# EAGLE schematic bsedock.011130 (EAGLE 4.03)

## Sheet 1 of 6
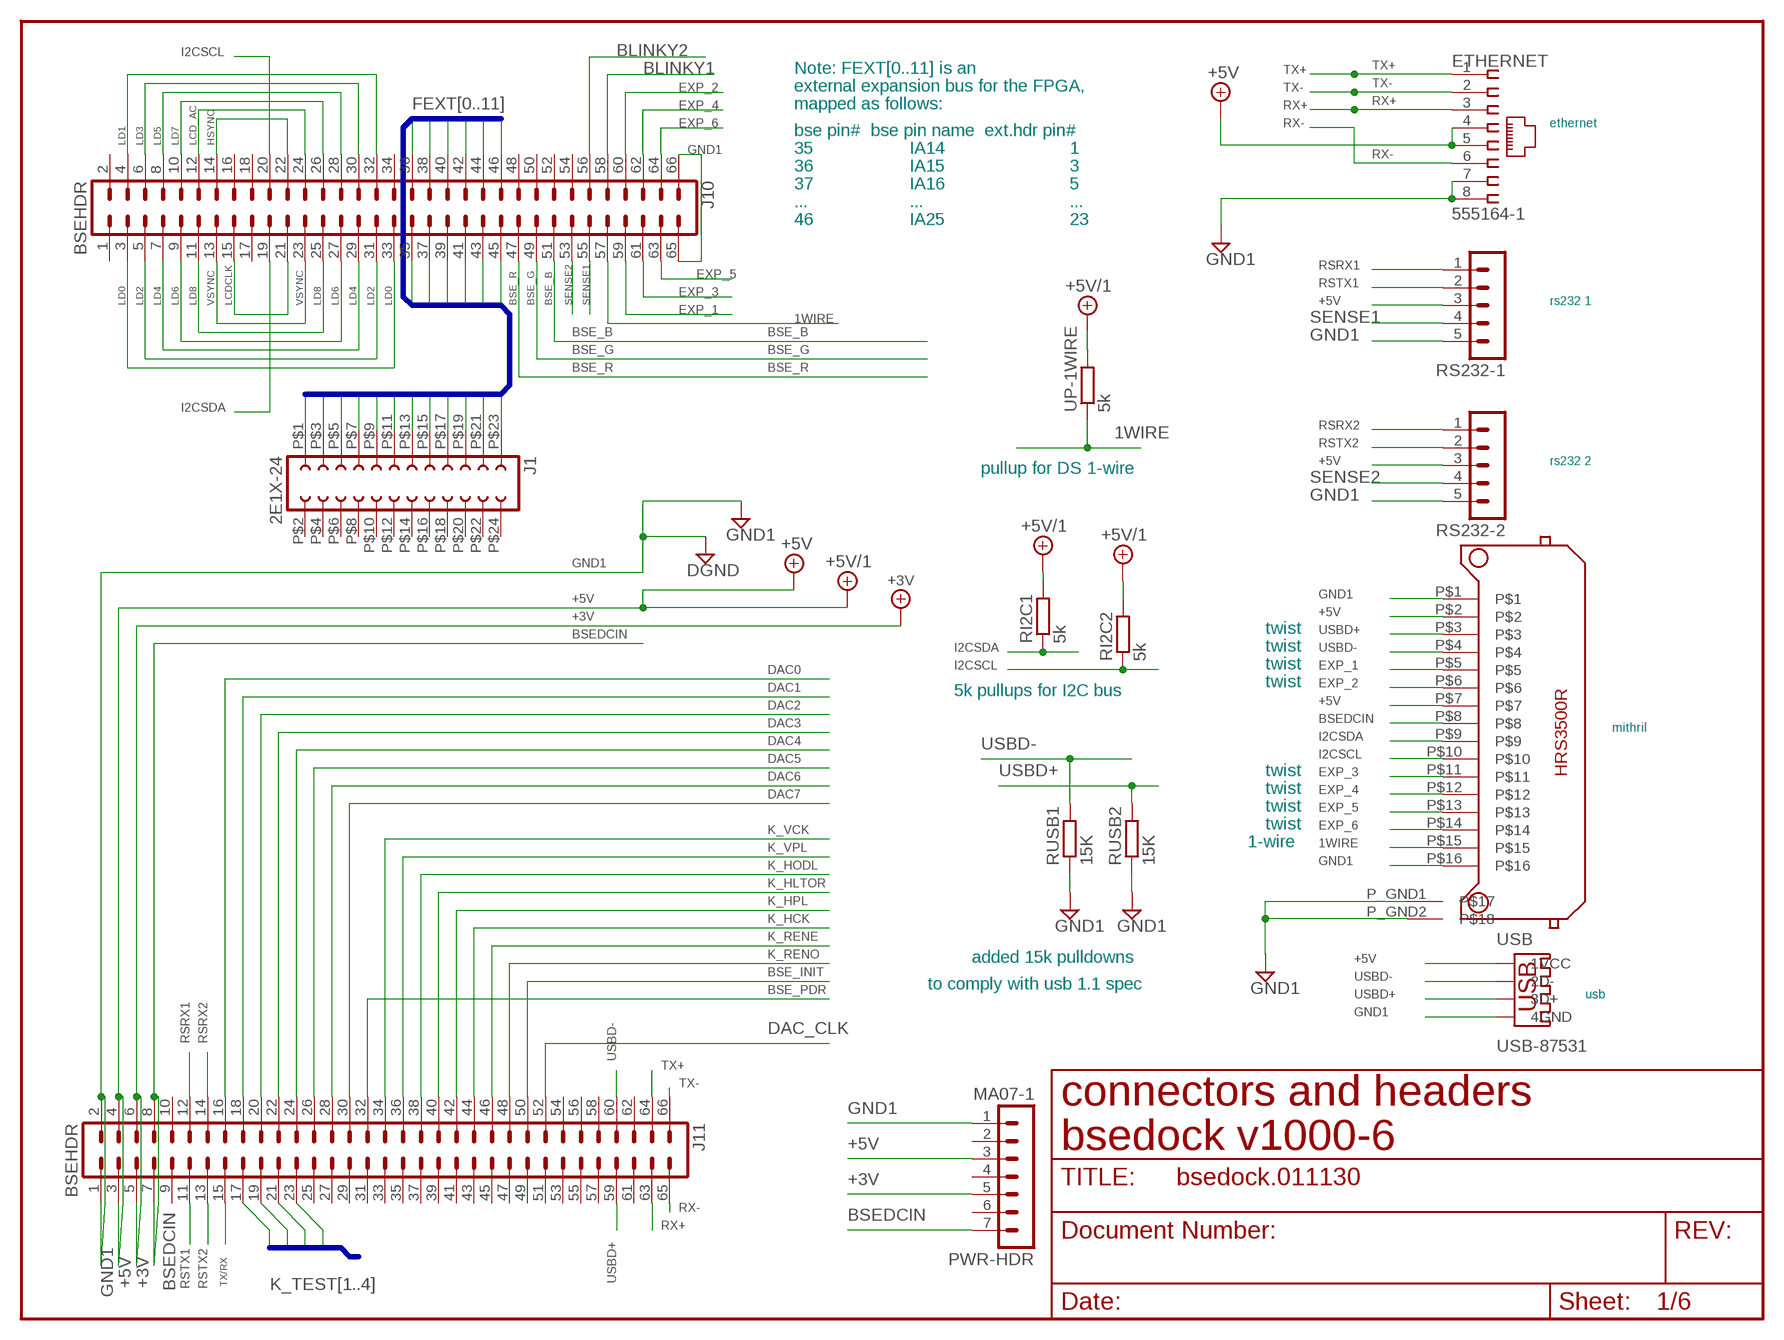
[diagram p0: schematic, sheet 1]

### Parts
BODY-BUS  HRS3500R  [HRS3500]
ETHERNET  555164-1  [555164-1]
J1  2E1X-24  [2E1X-24]
J10  BSEHDR  [BSEHDR]
J11  BSEHDR  [BSEHDR]
PWR-HDR  MA07-1  [MA07-1]
RI2C1  5k  R1206  [R1206]
RI2C2  5k  R1206  [R1206]
RS232-1  MA05-1  [MA05-1]
RS232-2  MA05-1  [MA05-1]
RUSB1  15K  R1206  [R1206]
RUSB2  15K  R1206  [R1206]
UP-1WIRE  5k  R1206  [R1206]
USB  USB-87531  [USB]

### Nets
1WIRE: BODY-BUS.P$15 J10.57 UP-1WIRE.1 ; also sheet 6
+3V: J11.5 J11.6 PWR-HDR.5 ; also sheet 2,4
+5V: BODY-BUS.P$2 BODY-BUS.P$7 ETHERNET.4 ETHERNET.5 J11.3 J11.4 PWR-HDR.3 RI2C1.2 RI2C2.2 RS232-1.3 RS232-2.3 UP-1WIRE.2 USB.1(1VCC) ; supply symbol labelled +5V/1 ; also sheet 2,3,4,5,6
BLINKY1: J10.58 ; also sheet 2
BLINKY2: J10.56 ; also sheet 2
BSE_B: J10.51 ; also sheet 4
BSE_G: J10.49 ; also sheet 4
BSE_INIT: J11.50 ; also sheet 4
BSE_PDR: J11.32 ; also sheet 4
BSE_R: J10.47 ; also sheet 4
BSEDCIN: BODY-BUS.P$8 J11.7 J11.8 PWR-HDR.7
DAC0: J11.16 ; also sheet 3
DAC1: J11.18 ; also sheet 3
DAC2: J11.20 ; also sheet 3
DAC3: J11.22 ; also sheet 3
DAC4: J11.24 ; also sheet 3
DAC5: J11.26 ; also sheet 3
DAC6: J11.28 ; also sheet 3
DAC7: J11.30 ; also sheet 3
DAC_CLK: J11.52 ; also sheet 3
EXP_1: BODY-BUS.P$5 J10.59
EXP_2: BODY-BUS.P$6 J10.60
EXP_3: BODY-BUS.P$11 J10.61
EXP_4: BODY-BUS.P$12 J10.62
EXP_5: BODY-BUS.P$13 J10.63
EXP_6: BODY-BUS.P$14 J10.64
FEXT0: J1.P$1 J10.35
FEXT1: J1.P$3 J10.36
FEXT2: J1.P$5 J10.37
FEXT3: J1.P$7 J10.38
FEXT4: J1.P$9 J10.39
FEXT5: J1.P$11 J10.40
FEXT6: J1.P$13 J10.41
FEXT7: J1.P$15 J10.42
FEXT8: J1.P$17 J10.43
FEXT9: J1.P$19 J10.44
FEXT10: J1.P$21 J10.45
FEXT11: J1.P$23 J10.46
GND1: BODY-BUS.P$1 BODY-BUS.P$16 BODY-BUS.P_GND1 BODY-BUS.P_GND2 ETHERNET.7 ETHERNET.8 J10.65 J10.66 J11.1 J11.2 PWR-HDR.1 RS232-1.5 RS232-2.5 RUSB1.1 RUSB2.1 USB.4(4GND) ; supply symbol labelled DGND ; also sheet 2,3,4,5,6
HSYNC: J10.14 J10.22
I2CSCL: BODY-BUS.P$10 J10.20 RI2C2.1
I2CSDA: BODY-BUS.P$9 J10.19 RI2C1.1
K_HCK: J11.44 ; also sheet 4
K_HLTOR: J11.40 ; also sheet 4
K_HODL: J11.38 ; also sheet 4
K_HPL: J11.42 ; also sheet 4
K_RENE: J11.46 ; also sheet 4
K_RENO: J11.48 ; also sheet 4
K_TEST1: J11.17 ; also sheet 4
K_TEST2: J11.19 ; also sheet 4
K_TEST3: J11.21 ; also sheet 4
K_TEST4: J11.23 ; also sheet 4
K_VCK: J11.34 ; also sheet 4
K_VPL: J11.36 ; also sheet 4
LCD_AC: J10.12 J10.24
LCDCLK: J10.15 J10.21
LD0: J10.3 J10.33
LD1: J10.4 J10.32
LD2: J10.5 J10.31
LD3: J10.6 J10.30
LD4: J10.7 J10.29
LD5: J10.8 J10.28
LD6: J10.9 J10.27
LD7: J10.10 J10.26
LD8: J10.11 J10.25
RSRX1: J11.12 RS232-1.1
RSRX2: J11.14 RS232-2.1
RSTX1: J11.11 RS232-1.2
RSTX2: J11.13 RS232-2.2
RX+: ETHERNET.3 J11.63
RX-: ETHERNET.6 J11.65
SENSE1: J10.55 RS232-1.4
SENSE2: J10.53 RS232-2.4
TX+: ETHERNET.1 J11.64
TX-: ETHERNET.2 J11.66
TX/RX: J11.15 ; also sheet 4
USBD+: BODY-BUS.P$3 J11.59 RUSB2.2 USB.3(3D+)
USBD-: BODY-BUS.P$4 J11.60 RUSB1.2 USB.2(2D-)
VSYNC: J10.13 J10.23
Unconnected: J1.P$2 J1.P$4 J1.P$6 J1.P$8 J1.P$10 J1.P$12 J1.P$14 J1.P$16 J1.P$18 J1.P$20 J1.P$22 J1.P$24 J10.1 J10.2 J10.16 J10.17 J10.18 J10.34 J10.48 J10.50 J10.52 J10.54 J11.9 J11.10 J11.25 J11.27 J11.29 J11.31 J11.33 J11.35 J11.37 J11.39 J11.41 J11.43 J11.45 J11.47 J11.49 J11.51 J11.53 J11.54 J11.55 J11.56 J11.57 J11.58 J11.61 J11.62 PWR-HDR.2 PWR-HDR.4 PWR-HDR.6

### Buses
FEXT[0..11]
K_TEST[1..4]

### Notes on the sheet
- Note: FEXT[0..11] is an
- external expansion bus for the FPGA,
- mapped as follows:
- ethernet
- bse pin#  bse pin name  ext.hdr pin#
- 35 | IA14 | 1
- 36 | IA15 | 3
- 37 | IA16 | 5
- ... | ... | ...
- 46 | IA25 | 23
- rs232 1
- rs232 2
- pullup for DS 1-wire
- twist
- twist
- twist
- twist
- 5k pullups for I2C bus
- mithril
- twist
- twist
- twist
- twist
- 1-wire
- added 15k pulldowns
- to comply with usb 1.1 spec
- usb
- connectors and headers
- bsedock v1000-6

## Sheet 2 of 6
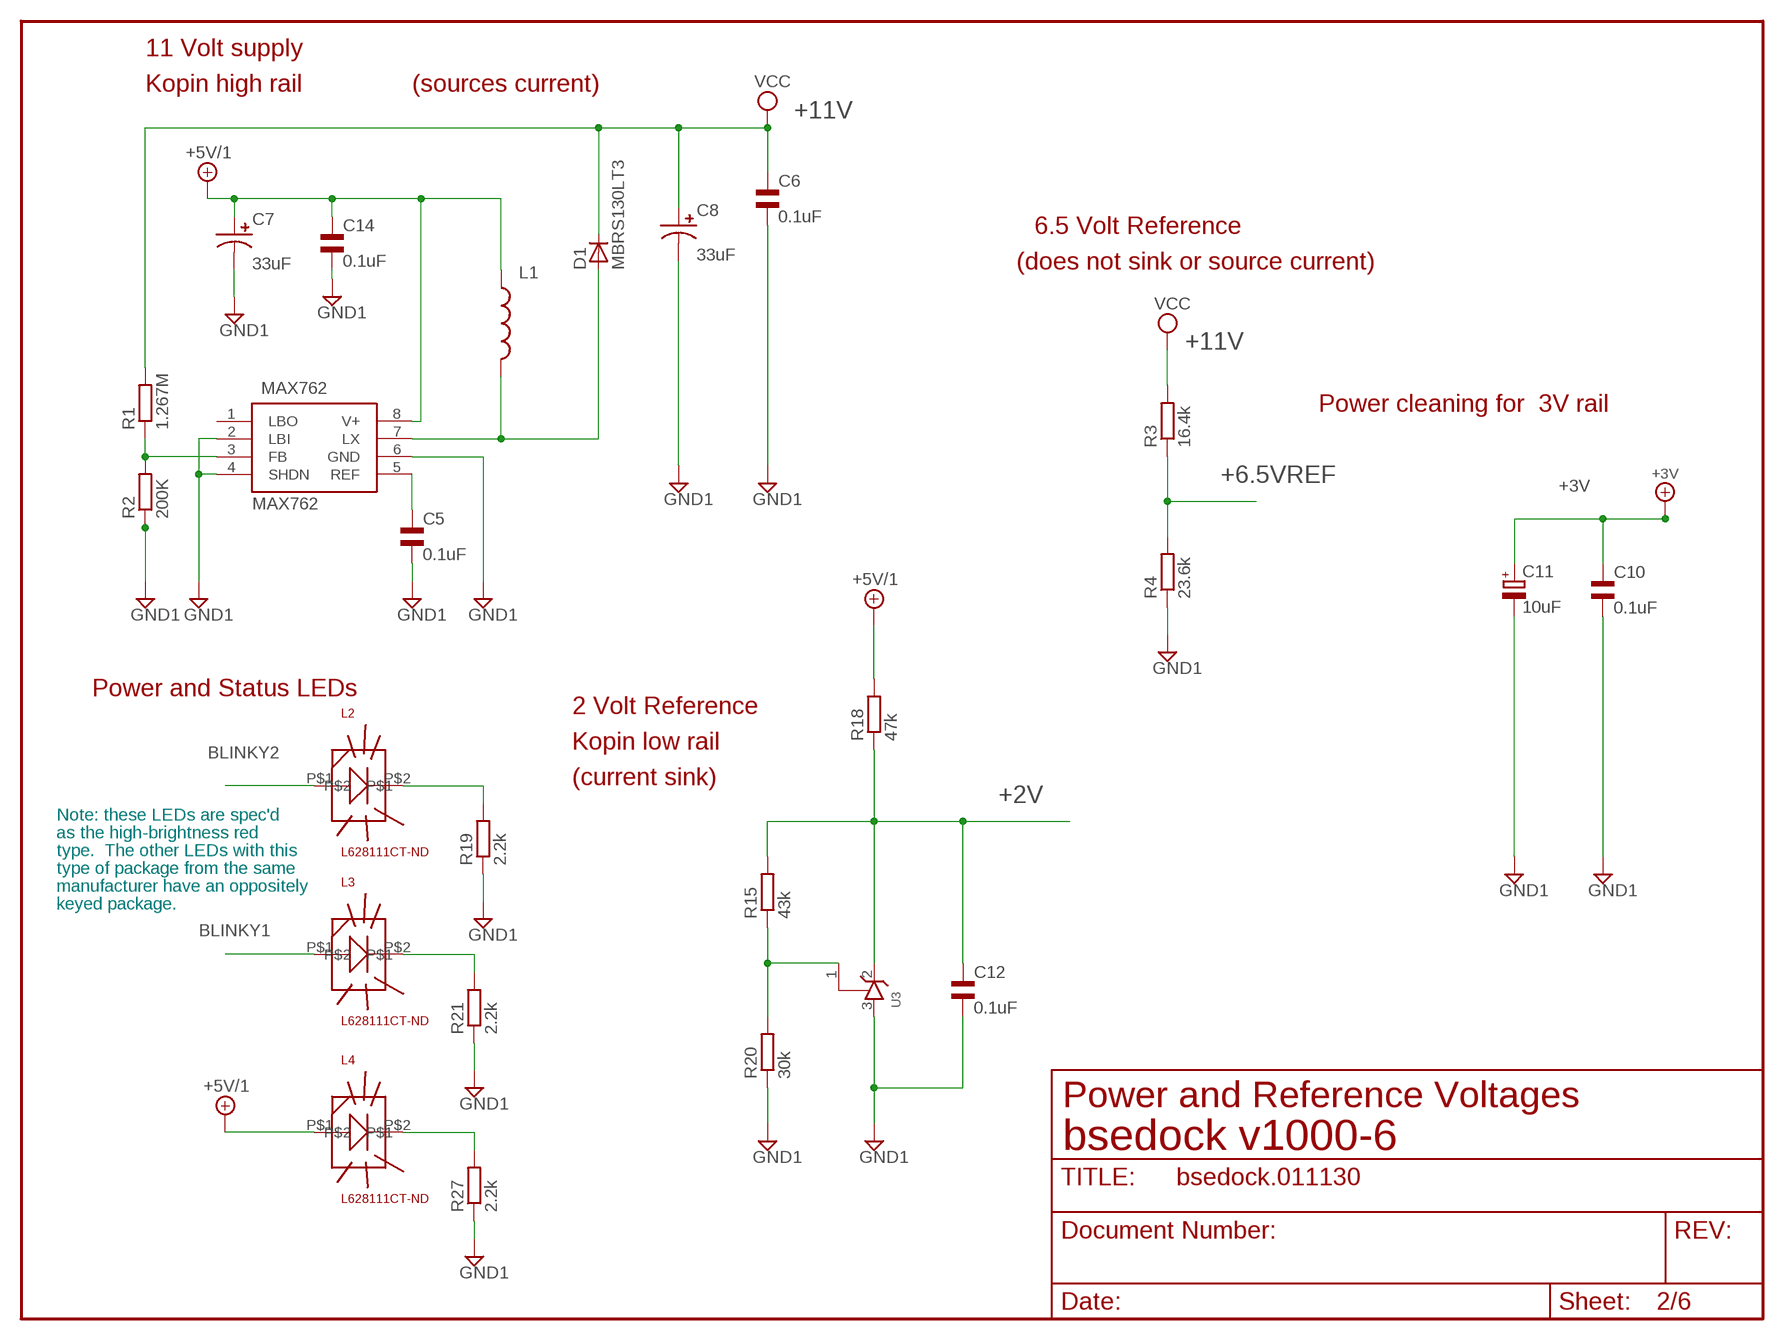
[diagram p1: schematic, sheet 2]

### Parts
C5  0.1uF  C1206  [C1206]
C6  0.1uF  C1206  [C1206]
C7  33uF  PAN-LY-C  [PAN-LY-C]
C8  33uF  PAN-LY-C  [PAN-LY-C]
C10  0.1uF  C1206  [C1206]
C11  10uF  CT7343  [CT7343]
C12  0.1uF  C1206  [C1206]
C14  0.1uF  C1206  [C1206]
D1  MBRS130LT3  SMB  [SMB]
L1  IND-D124C  [D124C]
L2  L628111CT-ND  L62711CTND  [L62711CT]
L3  L628111CT-ND  L62711CTND  [L62711CT]
L4  L628111CT-ND  L62711CTND  [L62711CT]
MAX762  MAX762  [SO08]
R1  1.267M  R1206  [R1206]
R2  200K  R1206  [R1206]
R3  16.4k  R1206  [R1206]
R4  23.6k  R1206  [R1206]
R15  43k  R1206  [R1206]
R18  47k  R1206  [R1206]
R19  2.2k  R1206  [R1206]
R20  30k  R1206  [R1206]
R21  2.2k  R1206  [R1206]
R27  2.2k  R1206  [R1206]
U3  4041CIM  [SOT23]

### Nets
+2V: C12.2 R15.2 R18.1 U3.2(C) ; also sheet 4
+3V: C10.2 C11.1(+) ; also sheet 1,4
+5V: C7.P+(+) C14.2 L1.P$1 L4.P$1 MAX762.8(V+) R18.2 ; supply symbol labelled +5V/1 ; also sheet 1,3,4,5,6
+6.5VREF: R3.1 R4.2 ; also sheet 4
+11V: C6.2 C8.P+(+) D1.1(K) R1.2 R3.2 ; supply symbol labelled VCC ; also sheet 4,5
BLINKY1: L3.P$1 ; also sheet 1
BLINKY2: L2.P$1 ; also sheet 1
GND1: C5.1 C6.1 C7.P-(-) C8.P-(-) C10.1 C11.2(-) C12.1 C14.1 MAX762.2(LBI) MAX762.4(SHDN) MAX762.6(GND) R2.1 R4.1 R19.1 R20.1 R21.1 R27.1 U3.3(A) ; also sheet 1,3,4,5,6
N$21: R15.1 R20.2 U3.1(R)
N$26: L2.P$2 R19.2
N$27: L3.P$2 R21.2
N$28: L4.P$2 R27.2
N$36: MAX762.3(FB) R1.1 R2.2
N$37: D1.2(A) L1.P$2 MAX762.7(LX)
N$38: C5.2 MAX762.5(REF)
Unconnected: MAX762.1(LBO)

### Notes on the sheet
- 11 Volt supply
- Kopin high rail | (sources current)
- 6.5 Volt Reference
- (does not sink or source current)
- Power cleaning for  3V rail
- Power and Status LEDs
- 2 Volt Reference
- Kopin low rail
- (current sink)
- Note: these LEDs are spec'd
- as the high-brightness red
- type.  The other LEDs with this
- type of package from the same
- manufacturer have an oppositely
- keyed package.
- Power and Reference Voltages
- bsedock v1000-6

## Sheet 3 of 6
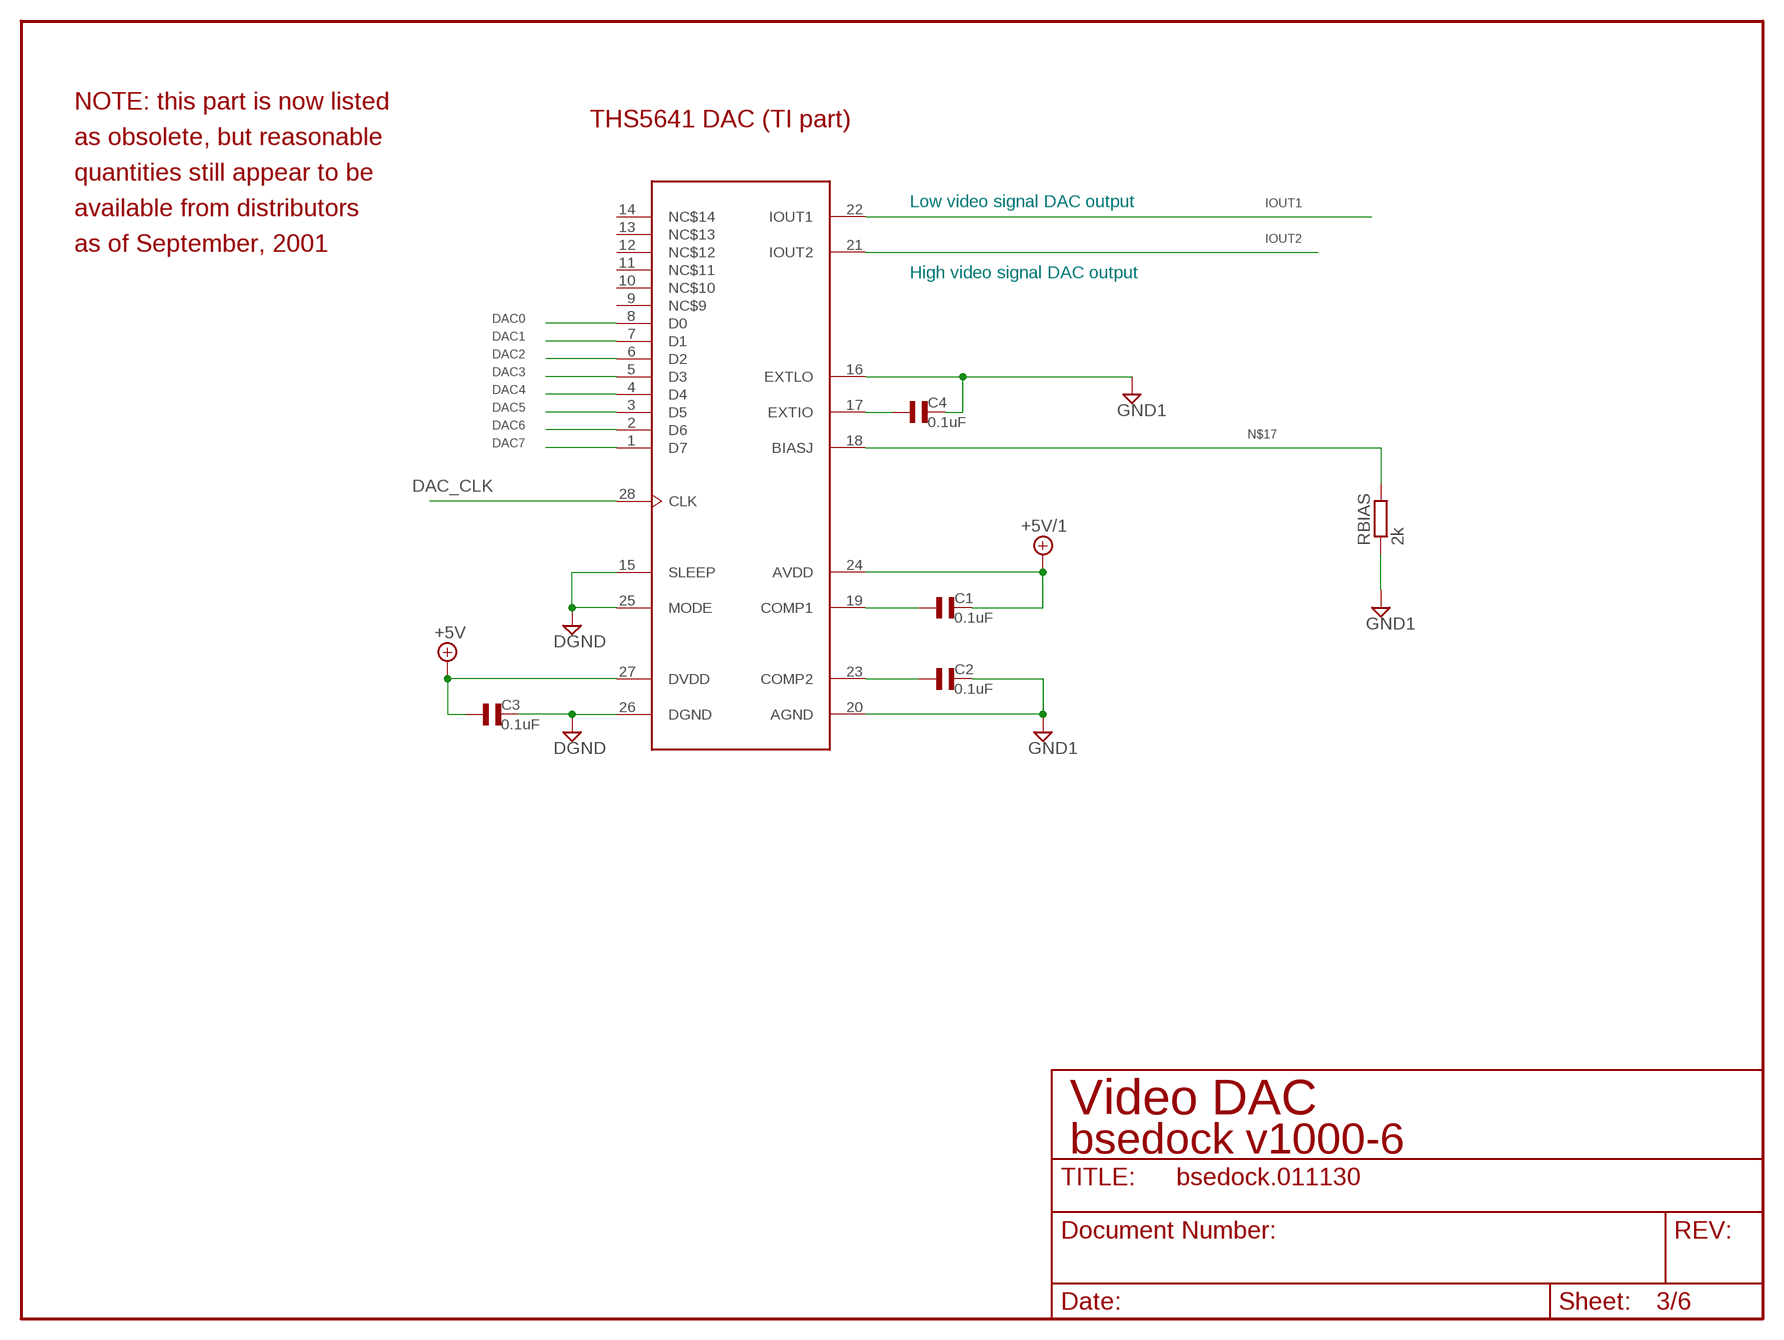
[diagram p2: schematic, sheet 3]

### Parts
C1  0.1uF  PCC1882  [1206]
C2  0.1uF  PCC1882  [1206]
C3  0.1uF  PCC1882  [1206]
C4  0.1uF  PCC1882  [1206]
DAC  THS5641IDW  [SMD-28]
RBIAS  2k  R1206  [R1206]

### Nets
+5V: C1.2 C3.1 DAC.24(AVDD) DAC.27(DVDD) ; supply symbol labelled +5V/1 ; also sheet 1,2,4,5,6
DAC0: DAC.8(D0) ; also sheet 1
DAC1: DAC.7(D1) ; also sheet 1
DAC2: DAC.6(D2) ; also sheet 1
DAC3: DAC.5(D3) ; also sheet 1
DAC4: DAC.4(D4) ; also sheet 1
DAC5: DAC.3(D5) ; also sheet 1
DAC6: DAC.2(D6) ; also sheet 1
DAC7: DAC.1(D7) ; also sheet 1
DAC_CLK: DAC.28(CLK) ; also sheet 1
GND1: C2.2 C3.2 C4.2 DAC.15(SLEEP) DAC.16(EXTLO) DAC.20(AGND) DAC.25(MODE) DAC.26(DGND) RBIAS.1 ; supply symbol labelled DGND ; also sheet 1,2,4,5,6
IOUT1: DAC.22(IOUT1) ; also sheet 5
IOUT2: DAC.21(IOUT2) ; also sheet 5
N$5: C1.1 DAC.19(COMP1)
N$7: C2.1 DAC.23(COMP2)
N$14: C4.1 DAC.17(EXTIO)
N$17: DAC.18(BIASJ) RBIAS.2
Unconnected: DAC.9(NC$9) DAC.10(NC$10) DAC.11(NC$11) DAC.12(NC$12) DAC.13(NC$13) DAC.14(NC$14)

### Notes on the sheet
- NOTE: this part is now listed
- THS5641 DAC (TI part)
- as obsolete, but reasonable
- quantities still appear to be
- Low video signal DAC output
- available from distributors
- as of September, 2001
- High video signal DAC output
- Video DAC
- bsedock v1000-6

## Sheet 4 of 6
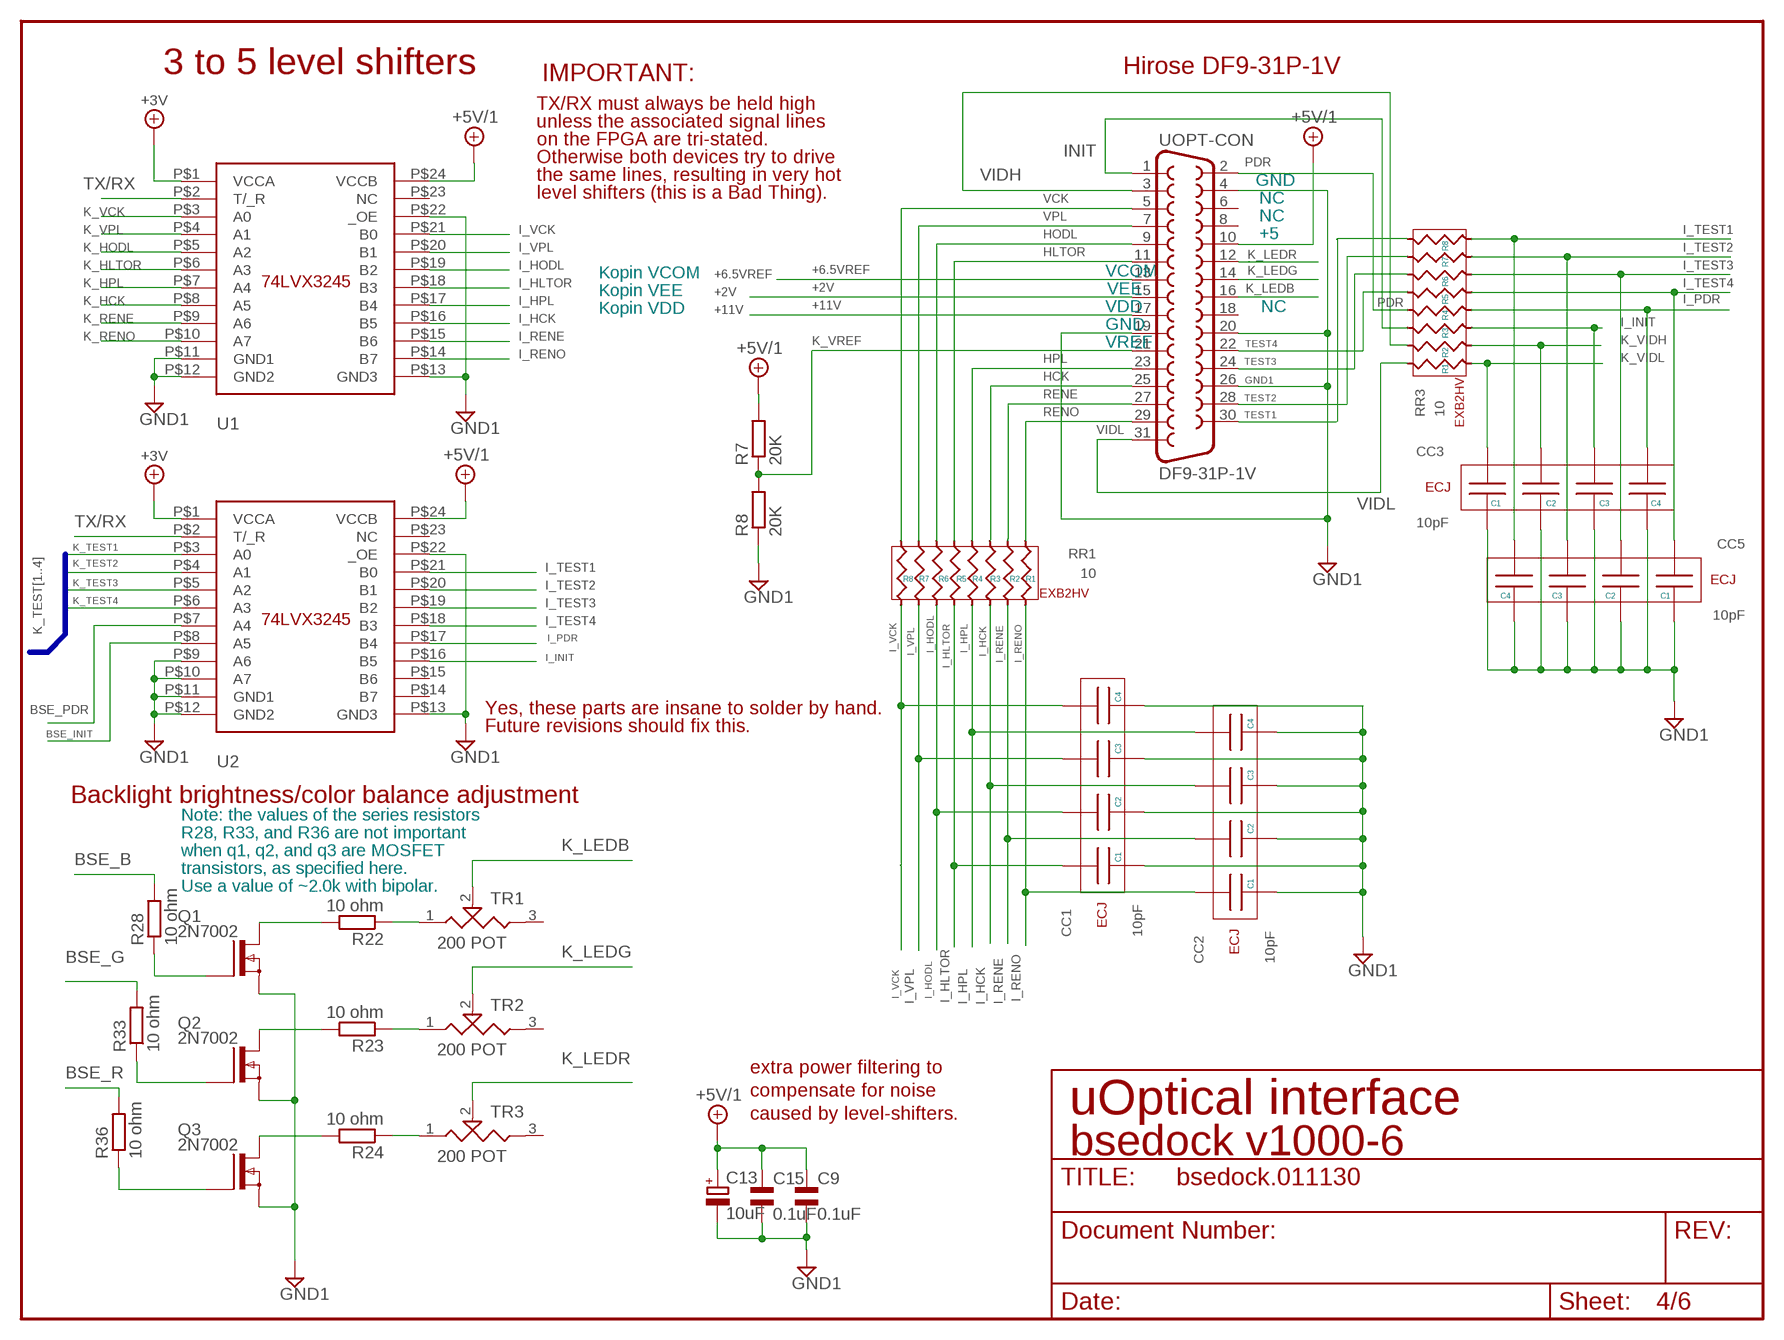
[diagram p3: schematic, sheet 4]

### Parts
C9  0.1uF  C1206  [C1206]
C13  10uF  CT7343  [CT7343]
C15  0.1uF  C1206  [C1206]
CC1  10pF  ECJRVC1H  [ECJRV]
CC2  10pF  ECJRVC1H  [ECJRV]
CC3  10pF  ECJRVC1H  [ECJRV]
CC5  10pF  ECJRVC1H  [ECJRV]
Q1  2N7002  [SOT23]
Q2  2N7002  [SOT23]
Q3  2N7002  [SOT23]
R7  20K  R1206  [R1206]
R8  20K  R1206  [R1206]
R22  10 ohm  R1206  [R1206]
R23  10 ohm  R1206  [R1206]
R24  10 ohm  R1206  [R1206]
R28  10 ohm  R1206  [R1206]
R33  10 ohm  R1206  [R1206]
R36  10 ohm  R1206  [R1206]
RR1  10  EXB2HVMAIN  [EXB2HV]
RR3  10  EXB2HVMAIN  [EXB2HV]
TR1  200 POT  P7JSMDPOT  [P7JSMTPO]
TR2  200 POT  P7JSMDPOT  [P7JSMTPO]
TR3  200 POT  P7JSMDPOT  [P7JSMTPO]
U1  74LVX3245QSCF  [QSOP24]
U2  74LVX3245QSCF  [QSOP24]
UOPT-CON  DF9-31P-1V  DF9-31S  [DF9-31S]

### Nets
+2V: UOPT-CON.15 ; also sheet 2
+3V: U1.P$1(VCCA) U2.P$1(VCCA) ; also sheet 1,2
+5V: C9.2 C13.1(+) C15.2 R7.2 U1.P$24(VCCB) U2.P$24(VCCB) UOPT-CON.10 ; supply symbol labelled +5V/1 ; also sheet 1,2,3,5,6
+6.5VREF: UOPT-CON.13 ; also sheet 2
+11V: UOPT-CON.17 ; also sheet 2,5
BSE_B: R28.2 ; also sheet 1
BSE_G: R33.2 ; also sheet 1
BSE_INIT: U2.P$8(A5) ; also sheet 1
BSE_PDR: U2.P$7(A4) ; also sheet 1
BSE_R: R36.2 ; also sheet 1
GND1: C9.1 C13.2(-) C15.1 CC1.P$1(C1A) CC1.P$2(C2A) CC1.P$3(C3A) CC1.P$4(C4A) CC2.P$1(C1A) CC2.P$2(C2A) CC2.P$3(C3A) CC2.P$4(C4A) CC3.P$1(C1A) CC3.P$2(C2A) CC3.P$3(C3A) CC3.P$4(C4A) CC5.P$1(C1A) CC5.P$2(C2A) CC5.P$3(C3A) CC5.P$4(C4A) Q1.2(S) Q2.2(S) Q3.2(S) R8.1 U1.P$11(GND1) U1.P$12(GND2) U1.P$13(GND3) U1.P$22(_OE) U2.P$9(A6) U2.P$10(A7) U2.P$11(GND1) U2.P$12(GND2) U2.P$13(GND3) U2.P$22(_OE) UOPT-CON.4 UOPT-CON.19 UOPT-CON.20 UOPT-CON.26 ; also sheet 1,2,3,5,6
HCK: RR1.P$14(R3B) UOPT-CON.25
HLTOR: RR1.P$12(R5B) UOPT-CON.11
HODL: RR1.P$11(R6B) UOPT-CON.9
HPL: RR1.P$13(R4B) UOPT-CON.23
I_HCK: CC2.P$6(C3B) RR1.P$3(R3A) U1.P$16(B5)
I_HLTOR: CC1.P$8(C1B) RR1.P$5(R5A) U1.P$18(B3)
I_HODL: CC1.P$7(C2B) RR1.P$6(R6A) U1.P$19(B2)
I_HPL: CC2.P$5(C4B) RR1.P$4(R4A) U1.P$17(B4)
I_INIT: CC3.P$6(C3B) RR3.P$3(R3A) U2.P$16(B5)
I_PDR: CC3.P$5(C4B) RR3.P$4(R4A) U2.P$17(B4)
I_RENE: CC2.P$7(C2B) RR1.P$2(R2A) U1.P$15(B6)
I_RENO: CC2.P$8(C1B) RR1.P$1(R1A) U1.P$14(B7)
I_TEST1: CC5.P$5(C4B) RR3.P$8(R8A) U2.P$21(B0)
I_TEST2: CC5.P$6(C3B) RR3.P$7(R7A) U2.P$20(B1)
I_TEST3: CC5.P$7(C2B) RR3.P$6(R6A) U2.P$19(B2)
I_TEST4: CC5.P$8(C1B) RR3.P$5(R5A) U2.P$18(B3)
I_VCK: CC1.P$5(C4B) RR1.P$8(R8A) U1.P$21(B0)
I_VPL: CC1.P$6(C3B) RR1.P$7(R7A) U1.P$20(B1)
INIT: RR3.P$14(R3B) UOPT-CON.1
K_HCK: U1.P$8(A5) ; also sheet 1
K_HLTOR: U1.P$6(A3) ; also sheet 1
K_HODL: U1.P$5(A2) ; also sheet 1
K_HPL: U1.P$7(A4) ; also sheet 1
K_LEDB: TR1.2 UOPT-CON.16
K_LEDG: TR2.2 UOPT-CON.14
K_LEDR: TR3.2 UOPT-CON.12
K_RENE: U1.P$9(A6) ; also sheet 1
K_RENO: U1.P$10(A7) ; also sheet 1
K_TEST1: U2.P$3(A0) ; also sheet 1
K_TEST2: U2.P$4(A1) ; also sheet 1
K_TEST3: U2.P$5(A2) ; also sheet 1
K_TEST4: U2.P$6(A3) ; also sheet 1
K_VCK: U1.P$3(A0) ; also sheet 1
K_VIDH: CC3.P$7(C2B) RR3.P$2(R2A) ; also sheet 5
K_VIDL: CC3.P$8(C1B) RR3.P$1(R1A) ; also sheet 5
K_VPL: U1.P$4(A1) ; also sheet 1
K_VREF: R7.1 R8.2 UOPT-CON.21
N$2: R22.1 TR1.1
N$3: R23.1 TR2.1
N$4: R24.1 TR3.1
N$6: Q1.3(D) R22.2
N$25: Q1.1(G) R28.1
N$31: Q2.1(G) R33.1
N$34: Q3.1(G) R36.1
N$47: Q2.3(D) R23.2
N$49: Q3.3(D) R24.2
PDR: RR3.P$13(R4B) UOPT-CON.2
RENE: RR1.P$15(R2B) UOPT-CON.27
RENO: RR1.P$16(R1B) UOPT-CON.29
TEST1: RR3.P$9(R8B) UOPT-CON.30
TEST2: RR3.P$10(R7B) UOPT-CON.28
TEST3: RR3.P$11(R6B) UOPT-CON.24
TEST4: RR3.P$12(R5B) UOPT-CON.22
TX/RX: U1.P$2(T/_R) U2.P$2(T/_R) ; also sheet 1
VCK: RR1.P$9(R8B) UOPT-CON.5
VIDH: RR3.P$15(R2B) UOPT-CON.3
VIDL: RR3.P$16(R1B) UOPT-CON.31
VPL: RR1.P$10(R7B) UOPT-CON.7
Unconnected: TR1.3 TR2.3 TR3.3 U1.P$23(NC) U2.P$14(B7) U2.P$15(B6) U2.P$23(NC) UOPT-CON.6 UOPT-CON.8 UOPT-CON.18

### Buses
K_TEST[1..4]

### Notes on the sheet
- 3 to 5 level shifters | Hirose DF9-31P-1V
- IMPORTANT:
- TX/RX must always be held high
- unless the associated signal lines
- on the FPGA are tri-stated.
- Otherwise both devices try to drive
- the same lines, resulting in very hot
- GND
- level shifters (this is a Bad Thing).
- NC
- NC
- +5
- Kopin VCOM | VCOM
- Kopin VEE | VEE
- Kopin VDD | VDD | NC
- GND
- VREF
- Yes, these parts are insane to solder by hand.
- Future revisions should fix this.
- Backlight brightness/color balance adjustment
- Note: the values of the series resistors
- R28, R33, and R36 are not important
- when q1, q2, and q3 are MOSFET
- transistors, as specified here.
- Use a value of ~2.0k with bipolar.
- extra power filtering to
- compensate for noise
- caused by level-shifters. | uOptical interface
- bsedock v1000-6

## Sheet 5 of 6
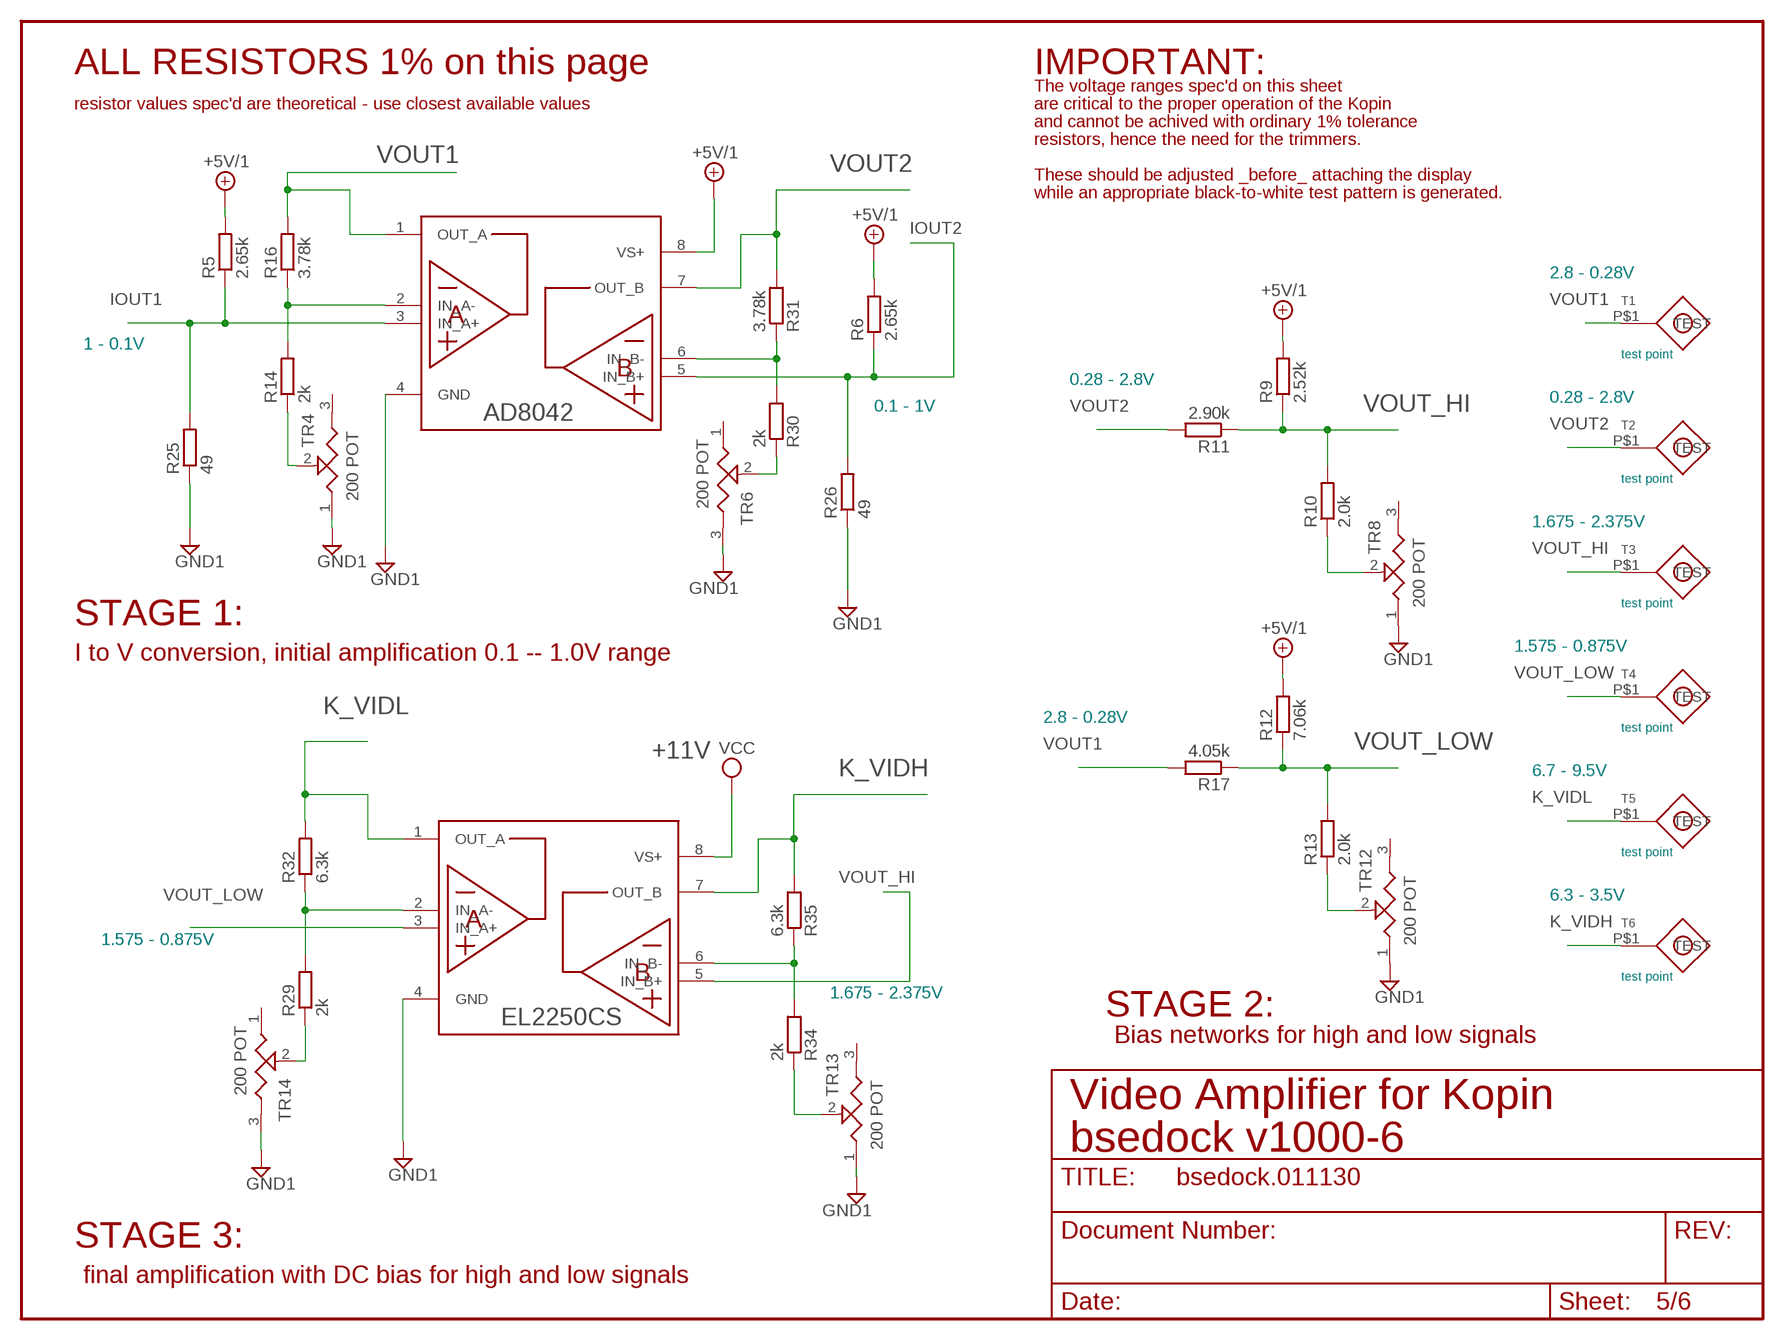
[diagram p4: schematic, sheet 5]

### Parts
AMP1  AD8042AR  [SO08]
AMP2  EL2250CS  [SO08]
R5  2.65k  R1206  [R1206]
R6  2.65k  R1206  [R1206]
R9  2.52k  R1206  [R1206]
R10  2.0k  R1206  [R1206]
R11  2.90k  R1206  [R1206]
R12  7.06k  R1206  [R1206]
R13  2.0k  R1206  [R1206]
R14  2k  R1206  [R1206]
R16  3.78k  R1206  [R1206]
R17  4.05k  R1206  [R1206]
R25  49  R1206  [R1206]
R26  49  R1206  [R1206]
R29  2k  R1206  [R1206]
R30  2k  R1206  [R1206]
R31  3.78k  R1206  [R1206]
R32  6.3k  R1206  [R1206]
R34  2k  R1206  [R1206]
R35  6.3k  R1206  [R1206]
T1  TEST  [TEST]
T2  TEST  [TEST]
T3  TEST  [TEST]
T4  TEST  [TEST]
T5  TEST  [TEST]
T6  TEST  [TEST]
TR4  200 POT  P7JSMDPOT  [P7JSMTPO]
TR6  200 POT  P7JSMDPOT  [P7JSMTPO]
TR8  200 POT  P7JSMDPOT  [P7JSMTPO]
TR12  200 POT  P7JSMDPOT  [P7JSMTPO]
TR13  200 POT  P7JSMDPOT  [P7JSMTPO]
TR14  200 POT  P7JSMDPOT  [P7JSMTPO]

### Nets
+5V: AMP1.8(VS+) R5.2 R6.2 R9.2 R12.2 ; supply symbol labelled +5V/1 ; also sheet 1,2,3,4,6
+11V: AMP2.8(VS+) ; supply symbol labelled VCC ; also sheet 2,4
GND1: AMP1.4(GND) AMP2.4(GND) R25.1 R26.1 TR4.1 TR6.3 TR8.1 TR12.1 TR13.1 TR14.3 ; also sheet 1,2,3,4,6
IOUT1: AMP1.3(IN_A+) R5.1 R25.2 ; also sheet 3
IOUT2: AMP1.5(IN_B+) R6.1 R26.2 ; also sheet 3
K_VIDH: AMP2.7(OUT_B) R35.2 T6.P$1(TEST) ; also sheet 4
K_VIDL: AMP2.1(OUT_A) R32.2 T5.P$1(TEST) ; also sheet 4
N$1: R14.1 TR4.2
N$8: AMP2.2(IN_A-) R29.2 R32.1
N$11: R30.1 TR6.2
N$12: AMP1.2(IN_A-) R14.2 R16.1
N$13: R10.1 TR8.2
N$15: AMP2.6(IN_B-) R34.2 R35.1
N$16: R13.1 TR12.2
N$18: R29.1 TR14.2
N$19: R34.1 TR13.2
N$20: AMP1.6(IN_B-) R30.2 R31.1
VOUT1: AMP1.1(OUT_A) R16.2 R17.2 T1.P$1(TEST)
VOUT2: AMP1.7(OUT_B) R11.2 R31.2 T2.P$1(TEST)
VOUT_HI: AMP2.5(IN_B+) R9.1 R10.2 R11.1 T3.P$1(TEST)
VOUT_LOW: AMP2.3(IN_A+) R12.1 R13.2 R17.1 T4.P$1(TEST)
Unconnected: TR4.3 TR6.1 TR8.3 TR12.3 TR13.3 TR14.1

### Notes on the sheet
- ALL RESISTORS 1% on this page | IMPORTANT:
- The voltage ranges spec'd on this sheet
- resistor values spec'd are theoretical - use closest available values | are critical to the proper operation of the Kopin
- and cannot be achived with ordinary 1% tolerance
- resistors, hence the need for the trimmers.
- These should be adjusted _before_ attaching the display
- while an appropriate black-to-white test pattern is generated.
- 2.8 - 0.28V
- 1 - 0.1V
- 0.28 - 2.8V
- 0.28 - 2.8V
- 0.1 - 1V
- 1.675 - 2.375V
- STAGE 1:
- 1.575 - 0.875V
- I to V conversion, initial amplification 0.1 -- 1.0V range
- 2.8 - 0.28V
- 6.7 - 9.5V
- 6.3 - 3.5V
- 1.575 - 0.875V
- 1.675 - 2.375V
- STAGE 2:
- Bias networks for high and low signals
- Video Amplifier for Kopin
- bsedock v1000-6
- STAGE 3:
- final amplification with DC bias for high and low signals

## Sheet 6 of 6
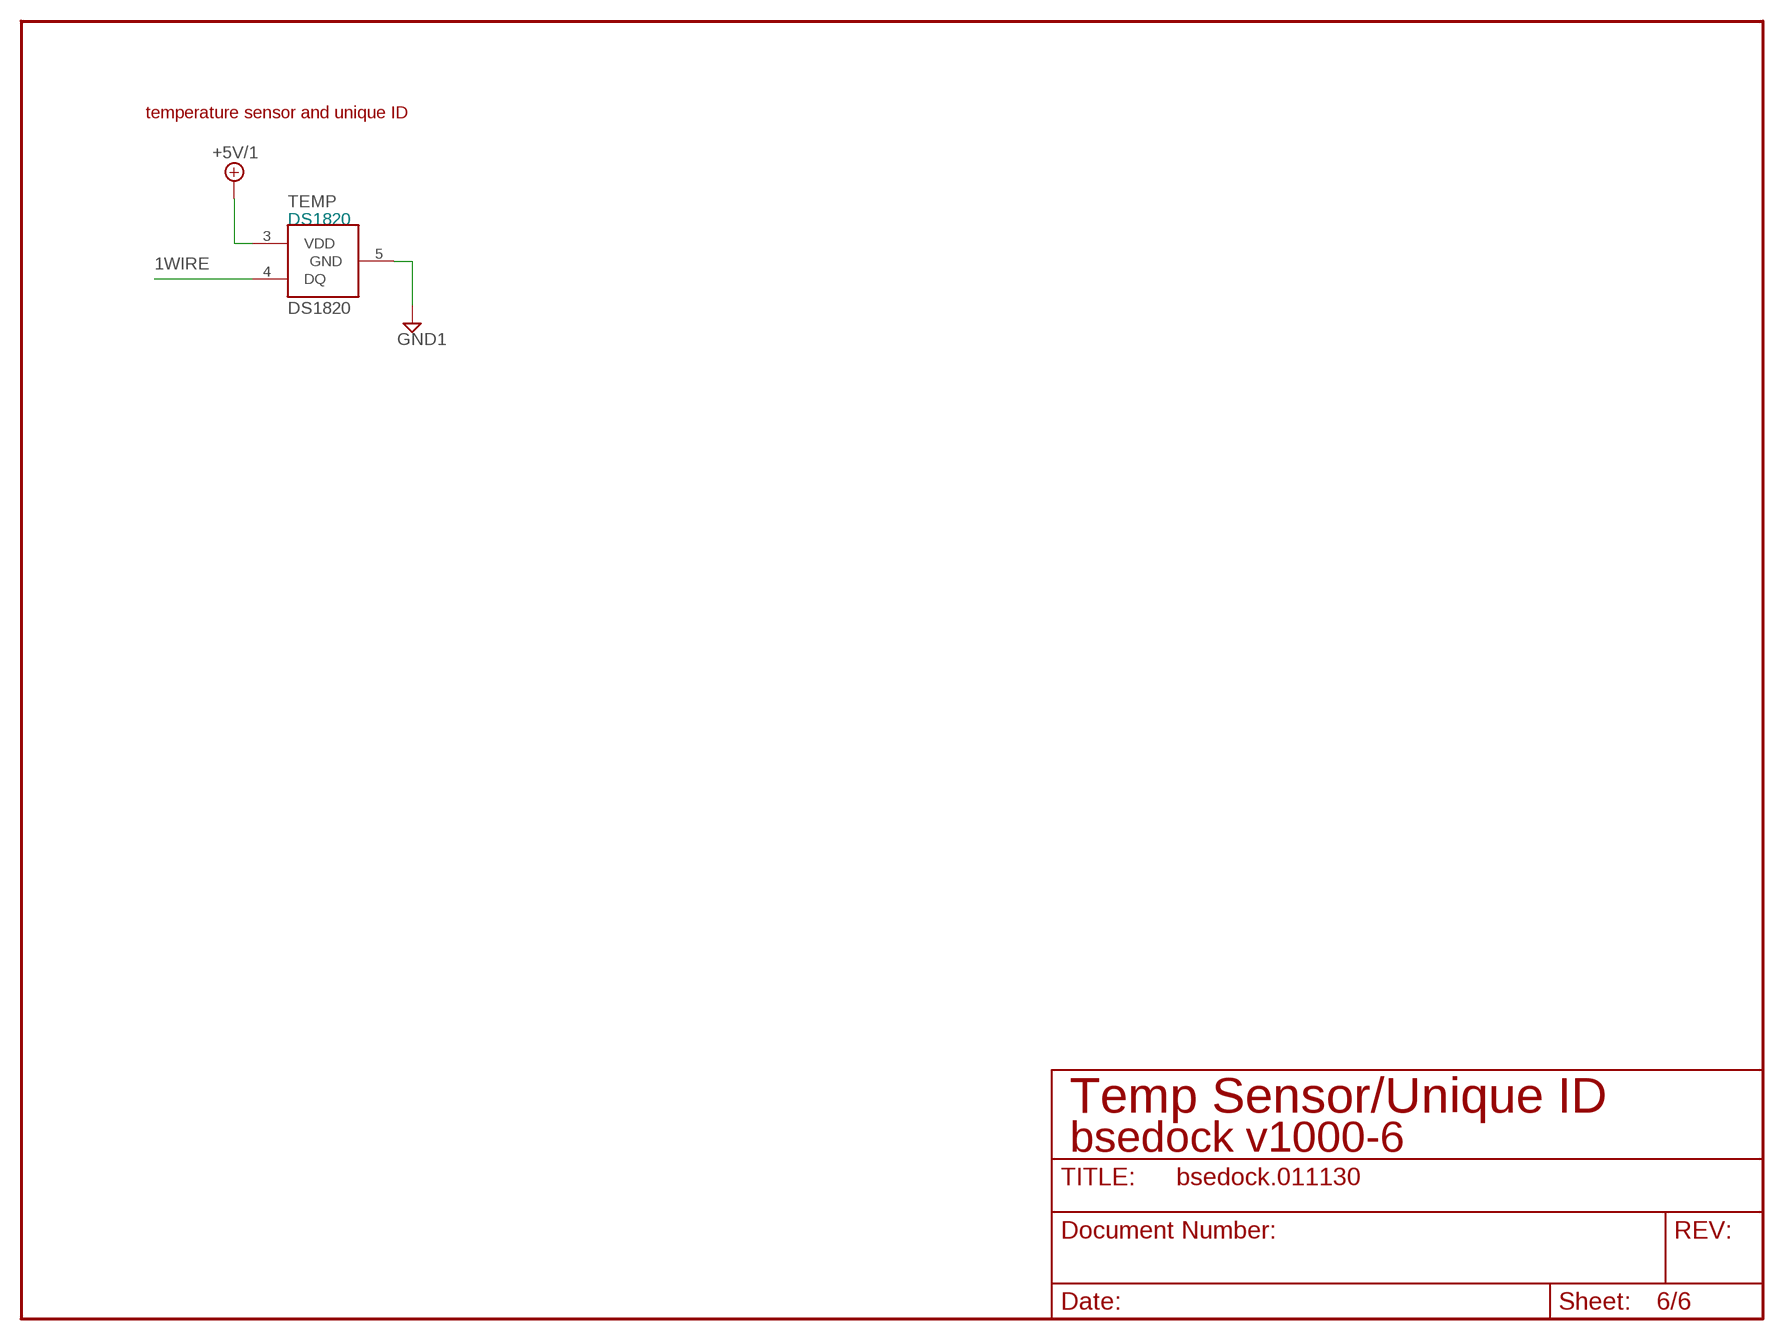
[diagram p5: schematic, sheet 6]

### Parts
TEMP  DS1820  [SO08]

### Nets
1WIRE: TEMP.4(DQ) ; also sheet 1
+5V: TEMP.3(VDD) ; supply symbol labelled +5V/1 ; also sheet 1,2,3,4,5
GND1: TEMP.5(GND) ; also sheet 1,2,3,4,5

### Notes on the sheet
- temperature sensor and unique ID
- Temp Sensor/Unique ID
- bsedock v1000-6

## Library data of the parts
AMP1 = woz:AD8042AR
AMP2 = woz:EL2250CS
BODY-BUS = evilb0rg:HRS3500R
C1-C4 = woz@3:PCC1882
C5 C6 C9 C10 C12 C14 C15 = ipc-rcl:C1206
C7 C8 = evilb0rg:PAN-LY-C
C11 C13 = ipc-rcl:CT7343
CC1-CC3 CC5 = evilb0rg:ECJRV: CAPACITOR ARRAY The Panasonic ECJ is an array of four independent capacitors in a single 1206 package.
D1 = ipc-rcl:SMB
DAC = woz@3:THS5641IDW
ETHERNET = amp-j:555164-1
J1 = woz:2E1X-24
J10 J11 = woz:BSEHDR
L1 = woz:IND-D124C
L2-L4 = evilb0rg:L62711CTND
MAX762 = woz@2:MAX762
PWR-HDR = evilcon-:MA07-1
Q1-Q3 = woz:2N7002
R1-R36 RBIAS RI2C1 RI2C2 RUSB1 RUSB2 UP-1WIRE = ipc-rcl:R1206
RR1 RR3 = evilb0rg:EXB2HV: Panasonic Resistor Array The EBX2HV is an array of independent resistors in a package almost too small to work with.
RS232-1 RS232-2 = evilcon-lstb:MA05-1
T1-T6 = evilb0rg:TEST
TEMP = woz:DS1820
TR1-TR4 TR6 TR8 TR12-TR14 = woz:P7JSMDPOT
U1 U2 = evilb0rg:74LVX3245QSC: CMOS/TTL level shifter The Fairchild 74VX3245QSC is a bidirectional translating transcever with tristateable outputs in a QSOP-24 package.
U3 = woz:4041CIM
UOPT-CON = HIROSE:DF9-31S
USB = woz:USB-87531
